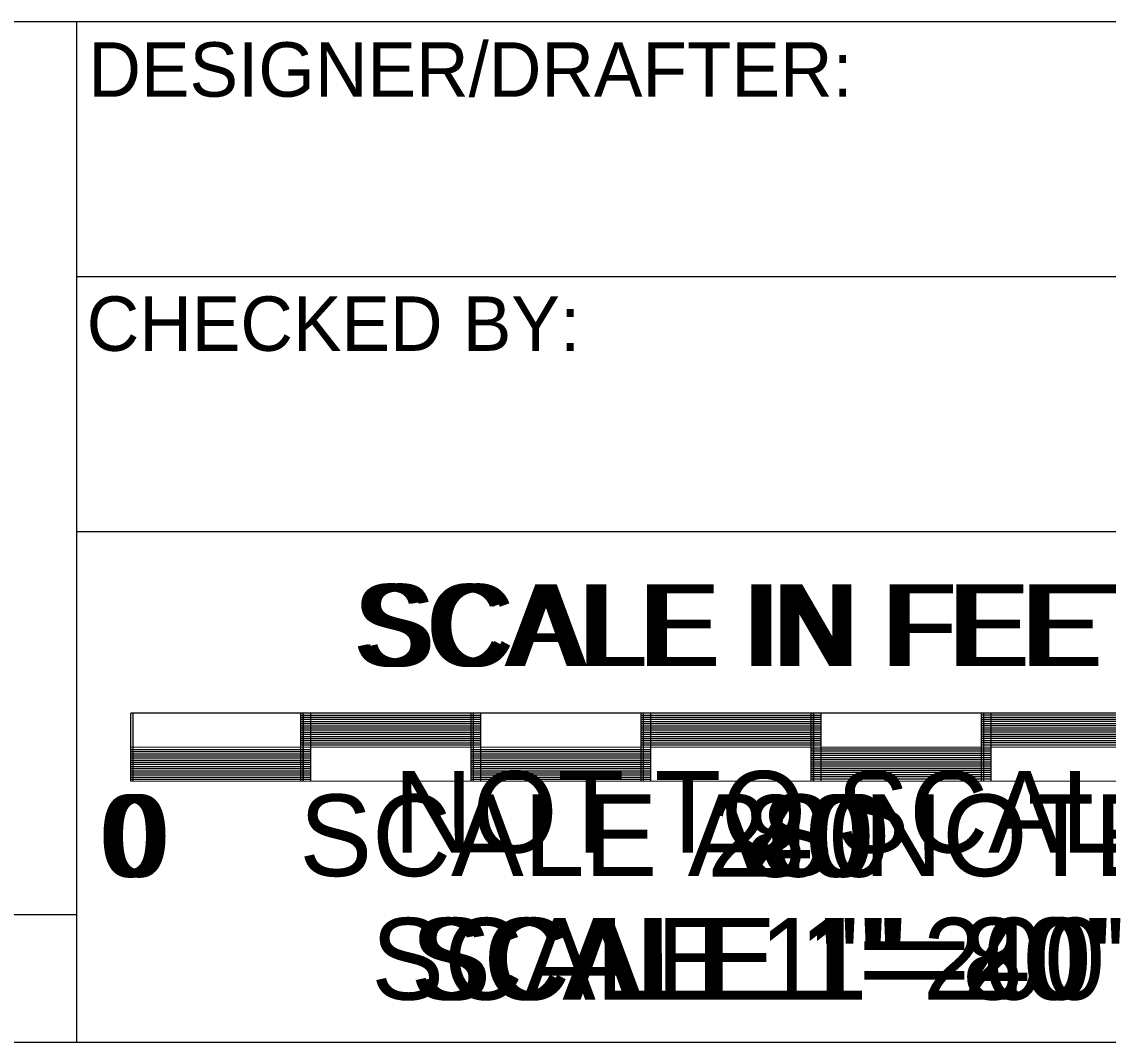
# Model space of a CAD drawing. Extents: x 0 to 2011, y -22 to 1183.
# Drawn here: x 341.3 to 405.2, y -1 to 59 of the extents above; entities that cross this region are included whole.
import ezdxf

# ---------------------------------------------------------------- set-up
doc = ezdxf.new("R2010")
doc.units = 0
for name, color, linetype in [('CT_Border_Perimeter_Shape', 7, 'Continuous'), ('CT_Scale_1_Inch_Equals_200_Feet', 7, 'Continuous'), ('CT_Scale_1_Inch_Equals_20_Feet', 7, 'Continuous'), ('CT_Scale_1_Inch_Equals_40_Feet', 7, 'Continuous'), ('CT_Scale_1_Inch_Equals_80_Feet', 7, 'Continuous'), ('CT_Scale_as_Noted', 7, 'Continuous'), ('CT_Title_Block_Linework', 7, 'Continuous'), ('CT_Title_Block_Text', 7, 'Continuous')]:
    doc.layers.add(name, color=color, linetype=linetype)

msp = doc.modelspace()

# ---------------------------------------------------------------- linework, layer by layer
at = {"layer": 'CT_Border_Perimeter_Shape'}
msp.add_lwpolyline([(0, -0.973), (1270, -0.973), (1270, 829.027), (0, 829.027)], close=True, dxfattribs=at)
at = {"layer": 'CT_Scale_1_Inch_Equals_200_Feet'}
for p, q in [((427.743, 18.378), (347.743, 18.378)), ((347.743, 14.384), (347.743, 18.378)), ((357.743, 14.385), (357.743, 18.378)), ((367.743, 18.242), (357.743, 18.242)), ((367.743, 18.118), (357.743, 18.118)), ((367.743, 17.994), (357.743, 17.994)), ((367.743, 14.385), (367.743, 18.378)), ((377.743, 14.386), (377.743, 18.378)), ((387.743, 18.242), (377.743, 18.242)), ((387.743, 18.118), (377.743, 18.118)), ((387.743, 17.994), (377.743, 17.994)), ((387.743, 14.398), (387.743, 18.378)), ((397.743, 14.398), (397.743, 18.378)), ((407.743, 18.254), (397.743, 18.254)), ((407.743, 18.13), (397.743, 18.13)), ((407.743, 18.002), (397.743, 18.002)), ((367.743, 17.87), (357.743, 17.87)), ((367.743, 17.742), (357.743, 17.742)), ((367.743, 17.618), (357.743, 17.618)), ((367.743, 17.494), (357.743, 17.494)), ((367.743, 17.37), (357.743, 17.37)), ((387.743, 17.87), (377.743, 17.87)), ((387.743, 17.742), (377.743, 17.742)), ((387.743, 17.618), (377.743, 17.618)), ((387.743, 17.494), (377.743, 17.494)), ((387.743, 17.37), (377.743, 17.37)), ((407.743, 17.878), (397.743, 17.878)), ((407.743, 17.754), (397.743, 17.754)), ((407.743, 17.63), (397.743, 17.63)), ((407.743, 17.502), (397.743, 17.502)), ((407.743, 17.378), (397.743, 17.378)), ((407.743, 17.254), (397.743, 17.254)), ((367.743, 17.242), (357.743, 17.242)), ((367.743, 17.118), (357.743, 17.118)), ((367.743, 16.994), (357.743, 16.994)), ((367.743, 16.87), (357.743, 16.87)), ((367.743, 16.742), (357.743, 16.742)), ((367.743, 16.618), (357.743, 16.618)), ((387.743, 17.242), (377.743, 17.242)), ((387.743, 17.118), (377.743, 17.118)), ((387.743, 16.994), (377.743, 16.994)), ((387.743, 16.87), (377.743, 16.87)), ((387.743, 16.742), (377.743, 16.742)), ((387.743, 16.618), (377.743, 16.618)), ((407.743, 17.13), (397.743, 17.13)), ((407.743, 17.002), (397.743, 17.002)), ((407.743, 16.878), (397.743, 16.878)), ((407.743, 16.754), (397.743, 16.754)), ((407.743, 16.63), (397.743, 16.63)), ((427.743, 16.39), (347.743, 16.364)), ((347.743, 16.242), (357.743, 16.242)), ((347.743, 16.118), (357.743, 16.118)), ((347.743, 15.994), (357.743, 15.994)), ((367.743, 16.494), (357.743, 16.494)), ((367.743, 16.242), (377.743, 16.242)), ((367.743, 16.118), (377.743, 16.118)), ((367.743, 15.994), (377.743, 15.994)), ((387.743, 16.494), (377.743, 16.494)), ((397.743, 16.256), (387.743, 16.256)), ((397.743, 16.132), (387.743, 16.132)), ((397.743, 16.004), (387.743, 16.004)), ((407.743, 16.502), (397.743, 16.502)), ((347.743, 15.87), (357.743, 15.87)), ((347.743, 15.742), (357.743, 15.742)), ((347.743, 15.618), (357.743, 15.618)), ((347.743, 15.494), (357.743, 15.494)), ((347.743, 15.37), (357.743, 15.37)), ((367.743, 15.87), (377.743, 15.87)), ((367.743, 15.742), (377.743, 15.742)), ((367.743, 15.618), (377.743, 15.618)), ((367.743, 15.494), (377.743, 15.494)), ((367.743, 15.37), (377.743, 15.37)), ((397.743, 15.88), (387.743, 15.88)), ((397.743, 15.88), (387.743, 15.88)), ((397.743, 15.756), (387.743, 15.756)), ((397.743, 15.632), (387.743, 15.632)), ((397.743, 15.504), (387.743, 15.504)), ((397.743, 15.38), (387.743, 15.38)), ((347.743, 15.242), (357.743, 15.242)), ((347.743, 15.118), (357.743, 15.118)), ((347.743, 14.994), (357.743, 14.994)), ((347.743, 14.87), (357.743, 14.87)), ((347.743, 14.742), (357.743, 14.742)), ((367.743, 15.242), (377.743, 15.242)), ((367.743, 15.118), (377.743, 15.118)), ((367.743, 14.994), (377.743, 14.994)), ((367.743, 14.87), (377.743, 14.87)), ((367.743, 14.742), (377.743, 14.742)), ((397.743, 15.256), (387.743, 15.256)), ((397.743, 15.132), (387.743, 15.132)), ((397.743, 15.004), (387.743, 15.004)), ((397.743, 14.88), (387.743, 14.88)), ((397.743, 14.756), (387.743, 14.756)), ((347.743, 14.618), (357.743, 14.618)), ((347.743, 14.494), (357.743, 14.494)), ((347.743, 14.384), (427.743, 14.39)), ((367.743, 14.618), (377.743, 14.618)), ((367.743, 14.494), (377.743, 14.494)), ((397.743, 14.632), (387.743, 14.632)), ((397.743, 14.504), (387.743, 14.504))]:
    msp.add_line(p, q, dxfattribs=at)
at = {"layer": 'CT_Scale_1_Inch_Equals_20_Feet'}
for p, q in [((427.888, 18.378), (347.888, 18.378)), ((347.888, 14.384), (347.888, 18.378)), ((357.888, 14.385), (357.888, 18.378)), ((367.888, 18.242), (357.888, 18.242)), ((367.888, 18.118), (357.888, 18.118)), ((367.888, 17.994), (357.888, 17.994)), ((367.888, 14.385), (367.888, 18.378)), ((377.888, 14.386), (377.888, 18.378)), ((387.888, 18.242), (377.888, 18.242)), ((387.888, 18.118), (377.888, 18.118)), ((387.888, 17.994), (377.888, 17.994)), ((387.888, 14.398), (387.888, 18.378)), ((397.888, 14.398), (397.888, 18.378)), ((407.888, 18.254), (397.888, 18.254)), ((407.888, 18.13), (397.888, 18.13)), ((407.888, 18.002), (397.888, 18.002)), ((367.888, 17.87), (357.888, 17.87)), ((367.888, 17.742), (357.888, 17.742)), ((367.888, 17.618), (357.888, 17.618)), ((367.888, 17.494), (357.888, 17.494)), ((367.888, 17.37), (357.888, 17.37)), ((387.888, 17.87), (377.888, 17.87)), ((387.888, 17.742), (377.888, 17.742)), ((387.888, 17.618), (377.888, 17.618)), ((387.888, 17.494), (377.888, 17.494)), ((387.888, 17.37), (377.888, 17.37)), ((407.888, 17.878), (397.888, 17.878)), ((407.888, 17.754), (397.888, 17.754)), ((407.888, 17.63), (397.888, 17.63)), ((407.888, 17.502), (397.888, 17.502)), ((407.888, 17.378), (397.888, 17.378)), ((407.888, 17.254), (397.888, 17.254)), ((367.888, 17.242), (357.888, 17.242)), ((367.888, 17.118), (357.888, 17.118)), ((367.888, 16.994), (357.888, 16.994)), ((367.888, 16.87), (357.888, 16.87)), ((367.888, 16.742), (357.888, 16.742)), ((367.888, 16.618), (357.888, 16.618)), ((387.888, 17.242), (377.888, 17.242)), ((387.888, 17.118), (377.888, 17.118)), ((387.888, 16.994), (377.888, 16.994)), ((387.888, 16.87), (377.888, 16.87)), ((387.888, 16.742), (377.888, 16.742)), ((387.888, 16.618), (377.888, 16.618)), ((407.888, 17.13), (397.888, 17.13)), ((407.888, 17.002), (397.888, 17.002)), ((407.888, 16.878), (397.888, 16.878)), ((407.888, 16.754), (397.888, 16.754)), ((407.888, 16.63), (397.888, 16.63)), ((427.888, 16.39), (347.888, 16.364)), ((347.888, 16.242), (357.888, 16.242)), ((347.888, 16.118), (357.888, 16.118)), ((347.888, 15.994), (357.888, 15.994)), ((367.888, 16.494), (357.888, 16.494)), ((367.888, 16.242), (377.888, 16.242)), ((367.888, 16.118), (377.888, 16.118)), ((367.888, 15.994), (377.888, 15.994)), ((387.888, 16.494), (377.888, 16.494)), ((397.888, 16.256), (387.888, 16.256)), ((397.888, 16.132), (387.888, 16.132)), ((397.888, 16.004), (387.888, 16.004)), ((407.888, 16.502), (397.888, 16.502)), ((347.888, 15.87), (357.888, 15.87)), ((347.888, 15.742), (357.888, 15.742)), ((347.888, 15.618), (357.888, 15.618)), ((347.888, 15.494), (357.888, 15.494)), ((347.888, 15.37), (357.888, 15.37)), ((367.888, 15.87), (377.888, 15.87)), ((367.888, 15.742), (377.888, 15.742)), ((367.888, 15.618), (377.888, 15.618)), ((367.888, 15.494), (377.888, 15.494)), ((367.888, 15.37), (377.888, 15.37)), ((397.888, 15.88), (387.888, 15.88)), ((397.888, 15.88), (387.888, 15.88)), ((397.888, 15.756), (387.888, 15.756)), ((397.888, 15.632), (387.888, 15.632)), ((397.888, 15.504), (387.888, 15.504)), ((397.888, 15.38), (387.888, 15.38)), ((347.888, 15.242), (357.888, 15.242)), ((347.888, 15.118), (357.888, 15.118)), ((347.888, 14.994), (357.888, 14.994)), ((347.888, 14.87), (357.888, 14.87)), ((347.888, 14.742), (357.888, 14.742)), ((367.888, 15.242), (377.888, 15.242)), ((367.888, 15.118), (377.888, 15.118)), ((367.888, 14.994), (377.888, 14.994)), ((367.888, 14.87), (377.888, 14.87)), ((367.888, 14.742), (377.888, 14.742)), ((397.888, 15.256), (387.888, 15.256)), ((397.888, 15.132), (387.888, 15.132)), ((397.888, 15.004), (387.888, 15.004)), ((397.888, 14.88), (387.888, 14.88)), ((397.888, 14.756), (387.888, 14.756)), ((347.888, 14.618), (357.888, 14.618)), ((347.888, 14.494), (357.888, 14.494)), ((347.888, 14.384), (427.888, 14.39)), ((367.888, 14.618), (377.888, 14.618)), ((367.888, 14.494), (377.888, 14.494)), ((397.888, 14.632), (387.888, 14.632)), ((397.888, 14.504), (387.888, 14.504))]:
    msp.add_line(p, q, dxfattribs=at)
at = {"layer": 'CT_Scale_1_Inch_Equals_40_Feet'}
for p, q in [((428.32, 18.378), (348.32, 18.378)), ((358.32, 14.385), (358.32, 18.378)), ((368.32, 18.242), (358.32, 18.242)), ((368.32, 18.118), (358.32, 18.118)), ((368.32, 17.994), (358.32, 17.994)), ((368.32, 14.385), (368.32, 18.378)), ((378.32, 14.386), (378.32, 18.378)), ((388.32, 18.242), (378.32, 18.242)), ((388.32, 18.118), (378.32, 18.118)), ((388.32, 17.994), (378.32, 17.994)), ((388.32, 14.398), (388.32, 18.378)), ((398.32, 14.398), (398.32, 18.378)), ((408.32, 18.254), (398.32, 18.254)), ((408.32, 18.13), (398.32, 18.13)), ((408.32, 18.002), (398.32, 18.002)), ((368.32, 17.87), (358.32, 17.87)), ((368.32, 17.742), (358.32, 17.742)), ((368.32, 17.618), (358.32, 17.618)), ((368.32, 17.494), (358.32, 17.494)), ((368.32, 17.37), (358.32, 17.37)), ((388.32, 17.87), (378.32, 17.87)), ((388.32, 17.742), (378.32, 17.742)), ((388.32, 17.618), (378.32, 17.618)), ((388.32, 17.494), (378.32, 17.494)), ((388.32, 17.37), (378.32, 17.37)), ((408.32, 17.878), (398.32, 17.878)), ((408.32, 17.754), (398.32, 17.754)), ((408.32, 17.63), (398.32, 17.63)), ((408.32, 17.502), (398.32, 17.502)), ((408.32, 17.378), (398.32, 17.378)), ((408.32, 17.254), (398.32, 17.254)), ((368.32, 17.242), (358.32, 17.242)), ((368.32, 17.118), (358.32, 17.118)), ((368.32, 16.994), (358.32, 16.994)), ((368.32, 16.87), (358.32, 16.87)), ((368.32, 16.742), (358.32, 16.742)), ((368.32, 16.618), (358.32, 16.618)), ((388.32, 17.242), (378.32, 17.242)), ((388.32, 17.118), (378.32, 17.118)), ((388.32, 16.994), (378.32, 16.994)), ((388.32, 16.87), (378.32, 16.87)), ((388.32, 16.742), (378.32, 16.742)), ((388.32, 16.618), (378.32, 16.618)), ((408.32, 17.13), (398.32, 17.13)), ((408.32, 17.002), (398.32, 17.002)), ((408.32, 16.878), (398.32, 16.878)), ((408.32, 16.754), (398.32, 16.754)), ((408.32, 16.63), (398.32, 16.63)), ((428.32, 16.39), (348.32, 16.364)), ((348.32, 16.242), (358.32, 16.242)), ((348.32, 16.118), (358.32, 16.118)), ((348.32, 15.994), (358.32, 15.994)), ((368.32, 16.494), (358.32, 16.494)), ((368.32, 16.242), (378.32, 16.242)), ((368.32, 16.118), (378.32, 16.118)), ((368.32, 15.994), (378.32, 15.994)), ((388.32, 16.494), (378.32, 16.494)), ((398.32, 16.256), (388.32, 16.256)), ((398.32, 16.132), (388.32, 16.132)), ((398.32, 16.004), (388.32, 16.004)), ((408.32, 16.502), (398.32, 16.502)), ((348.32, 15.87), (358.32, 15.87)), ((348.32, 15.742), (358.32, 15.742)), ((348.32, 15.618), (358.32, 15.618)), ((348.32, 15.494), (358.32, 15.494)), ((348.32, 15.37), (358.32, 15.37)), ((368.32, 15.87), (378.32, 15.87)), ((368.32, 15.742), (378.32, 15.742)), ((368.32, 15.618), (378.32, 15.618)), ((368.32, 15.494), (378.32, 15.494)), ((368.32, 15.37), (378.32, 15.37)), ((398.32, 15.88), (388.32, 15.88)), ((398.32, 15.88), (388.32, 15.88)), ((398.32, 15.756), (388.32, 15.756)), ((398.32, 15.632), (388.32, 15.632)), ((398.32, 15.504), (388.32, 15.504)), ((398.32, 15.38), (388.32, 15.38)), ((348.32, 15.242), (358.32, 15.242)), ((348.32, 15.118), (358.32, 15.118)), ((348.32, 14.994), (358.32, 14.994)), ((348.32, 14.87), (358.32, 14.87)), ((348.32, 14.742), (358.32, 14.742)), ((368.32, 15.242), (378.32, 15.242)), ((368.32, 15.118), (378.32, 15.118)), ((368.32, 14.994), (378.32, 14.994)), ((368.32, 14.87), (378.32, 14.87)), ((368.32, 14.742), (378.32, 14.742)), ((398.32, 15.256), (388.32, 15.256)), ((398.32, 15.132), (388.32, 15.132)), ((398.32, 15.004), (388.32, 15.004)), ((398.32, 14.88), (388.32, 14.88)), ((398.32, 14.756), (388.32, 14.756)), ((348.32, 14.618), (358.32, 14.618)), ((348.32, 14.494), (358.32, 14.494)), ((348.32, 14.384), (428.32, 14.39)), ((368.32, 14.618), (378.32, 14.618)), ((368.32, 14.494), (378.32, 14.494)), ((398.32, 14.632), (388.32, 14.632)), ((398.32, 14.504), (388.32, 14.504))]:
    msp.add_line(p, q, dxfattribs=at)
at = {"layer": 'CT_Scale_1_Inch_Equals_80_Feet'}
for p, q in [((427.88, 18.378), (347.88, 18.378)), ((347.88, 14.384), (347.88, 18.378)), ((357.88, 14.385), (357.88, 18.378)), ((367.88, 18.242), (357.88, 18.242)), ((367.88, 18.118), (357.88, 18.118)), ((367.88, 17.994), (357.88, 17.994)), ((367.88, 14.385), (367.88, 18.378)), ((377.88, 14.386), (377.88, 18.378)), ((387.88, 18.242), (377.88, 18.242)), ((387.88, 18.118), (377.88, 18.118)), ((387.88, 17.994), (377.88, 17.994)), ((387.88, 14.398), (387.88, 18.378)), ((397.88, 14.398), (397.88, 18.378)), ((407.88, 18.254), (397.88, 18.254)), ((407.88, 18.13), (397.88, 18.13)), ((407.88, 18.002), (397.88, 18.002)), ((367.88, 17.87), (357.88, 17.87)), ((367.88, 17.742), (357.88, 17.742)), ((367.88, 17.618), (357.88, 17.618)), ((367.88, 17.494), (357.88, 17.494)), ((367.88, 17.37), (357.88, 17.37)), ((387.88, 17.87), (377.88, 17.87)), ((387.88, 17.742), (377.88, 17.742)), ((387.88, 17.618), (377.88, 17.618)), ((387.88, 17.494), (377.88, 17.494)), ((387.88, 17.37), (377.88, 17.37)), ((407.88, 17.878), (397.88, 17.878)), ((407.88, 17.754), (397.88, 17.754)), ((407.88, 17.63), (397.88, 17.63)), ((407.88, 17.502), (397.88, 17.502)), ((407.88, 17.378), (397.88, 17.378)), ((407.88, 17.254), (397.88, 17.254)), ((367.88, 17.242), (357.88, 17.242)), ((367.88, 17.118), (357.88, 17.118)), ((367.88, 16.994), (357.88, 16.994)), ((367.88, 16.87), (357.88, 16.87)), ((367.88, 16.742), (357.88, 16.742)), ((367.88, 16.618), (357.88, 16.618)), ((387.88, 17.242), (377.88, 17.242)), ((387.88, 17.118), (377.88, 17.118)), ((387.88, 16.994), (377.88, 16.994)), ((387.88, 16.87), (377.88, 16.87)), ((387.88, 16.742), (377.88, 16.742)), ((387.88, 16.618), (377.88, 16.618)), ((407.88, 17.13), (397.88, 17.13)), ((407.88, 17.002), (397.88, 17.002)), ((407.88, 16.878), (397.88, 16.878)), ((407.88, 16.754), (397.88, 16.754)), ((407.88, 16.63), (397.88, 16.63)), ((427.88, 16.39), (347.88, 16.364)), ((347.88, 16.242), (357.88, 16.242)), ((347.88, 16.118), (357.88, 16.118)), ((347.88, 15.994), (357.88, 15.994)), ((367.88, 16.494), (357.88, 16.494)), ((367.88, 16.242), (377.88, 16.242)), ((367.88, 16.118), (377.88, 16.118)), ((367.88, 15.994), (377.88, 15.994)), ((387.88, 16.494), (377.88, 16.494)), ((397.88, 16.256), (387.88, 16.256)), ((397.88, 16.132), (387.88, 16.132)), ((397.88, 16.004), (387.88, 16.004)), ((407.88, 16.502), (397.88, 16.502)), ((347.88, 15.87), (357.88, 15.87)), ((347.88, 15.742), (357.88, 15.742)), ((347.88, 15.618), (357.88, 15.618)), ((347.88, 15.494), (357.88, 15.494)), ((347.88, 15.37), (357.88, 15.37)), ((367.88, 15.87), (377.88, 15.87)), ((367.88, 15.742), (377.88, 15.742)), ((367.88, 15.618), (377.88, 15.618)), ((367.88, 15.494), (377.88, 15.494)), ((367.88, 15.37), (377.88, 15.37)), ((397.88, 15.88), (387.88, 15.88)), ((397.88, 15.88), (387.88, 15.88)), ((397.88, 15.756), (387.88, 15.756)), ((397.88, 15.632), (387.88, 15.632)), ((397.88, 15.504), (387.88, 15.504)), ((397.88, 15.38), (387.88, 15.38)), ((347.88, 15.242), (357.88, 15.242)), ((347.88, 15.118), (357.88, 15.118)), ((347.88, 14.994), (357.88, 14.994)), ((347.88, 14.87), (357.88, 14.87)), ((347.88, 14.742), (357.88, 14.742)), ((367.88, 15.242), (377.88, 15.242)), ((367.88, 15.118), (377.88, 15.118)), ((367.88, 14.994), (377.88, 14.994)), ((367.88, 14.87), (377.88, 14.87)), ((367.88, 14.742), (377.88, 14.742)), ((397.88, 15.256), (387.88, 15.256)), ((397.88, 15.132), (387.88, 15.132)), ((397.88, 15.004), (387.88, 15.004)), ((397.88, 14.88), (387.88, 14.88)), ((397.88, 14.756), (387.88, 14.756)), ((347.88, 14.618), (357.88, 14.618)), ((347.88, 14.494), (357.88, 14.494)), ((347.88, 14.384), (427.88, 14.39)), ((367.88, 14.618), (377.88, 14.618)), ((367.88, 14.494), (377.88, 14.494)), ((397.88, 14.632), (387.88, 14.632)), ((397.88, 14.504), (387.88, 14.504))]:
    msp.add_line(p, q, dxfattribs=at)
at = {"layer": 'CT_Title_Block_Linework'}
for p, q in [((1270, 59.027), (0, 59.027)), ((344.549, 59.027), (344.549, -0.973)), ((435.948, 44.027), (344.549, 44.027)), ((435.948, 29.027), (344.549, 29.027)), ((344.549, 6.527), (0, 6.527))]:
    msp.add_line(p, q, dxfattribs=at)

# ---------------------------------------------------------------- texts
at = {"layer": 'CT_Border_Perimeter_Shape'}
msp.add_text('NOT TO SCALE', height=4.8, dxfattribs=at).set_placement((363.195, 10.172))
at = {"layer": 'CT_Scale_1_Inch_Equals_200_Feet'}
for s, p in [('SCALE IN FEET', (360.792, 21.151)), ('0', (345.886, 8.757)), ('200', (381.63, 8.757))]:
    msp.add_text(s, height=4.8, dxfattribs=at).set_placement(p)
msp.add_text('SCALE 1"=200\'', height=4.8, rotation=0.01259, dxfattribs=at).set_placement((361.876, 1.532))
at = {"layer": 'CT_Scale_1_Inch_Equals_20_Feet'}
for s, p in [('SCALE IN FEET', (360.938, 21.151)), ('0', (346.032, 8.757)), ('20', (383.849, 8.757))]:
    msp.add_text(s, height=4.8, dxfattribs=at).set_placement(p)
msp.add_text('SCALE 1"=20\'', height=4.8, rotation=0.01259, dxfattribs=at).set_placement((364.205, 1.533))
at = {"layer": 'CT_Scale_1_Inch_Equals_40_Feet'}
for s, rotation, p in [('SCALE IN FEET', 360, (361.369, 21.151)), ('0', 360, (346.463, 8.757)), ('40', 360, (384.28, 8.757)), ('SCALE 1"=40\'', 0.01259, (364.636, 1.533))]:
    msp.add_text(s, height=4.8, rotation=rotation, dxfattribs=at).set_placement(p)
at = {"layer": 'CT_Scale_1_Inch_Equals_80_Feet'}
for s, p in [('SCALE IN FEET', (360.929, 21.151)), ('0', (346.024, 8.757)), ('80', (383.841, 8.757))]:
    msp.add_text(s, height=4.8, dxfattribs=at).set_placement(p)
msp.add_text('SCALE 1"=80\'', height=4.8, rotation=0.01259, dxfattribs=at).set_placement((364.197, 1.533))
at = {"layer": 'CT_Scale_as_Noted'}
msp.add_text('SCALE AS NOTED', height=4.8, dxfattribs=at).set_placement((357.647, 8.796))
at = {"layer": 'CT_Title_Block_Text'}
for s, p in [('DESIGNER/DRAFTER:', (345.249, 54.619)), ('CHECKED BY:', (345.147, 39.677))]:
    msp.add_text(s, height=3.2, rotation=360, dxfattribs=at).set_placement(p)

doc.saveas('drawing.dxf')
